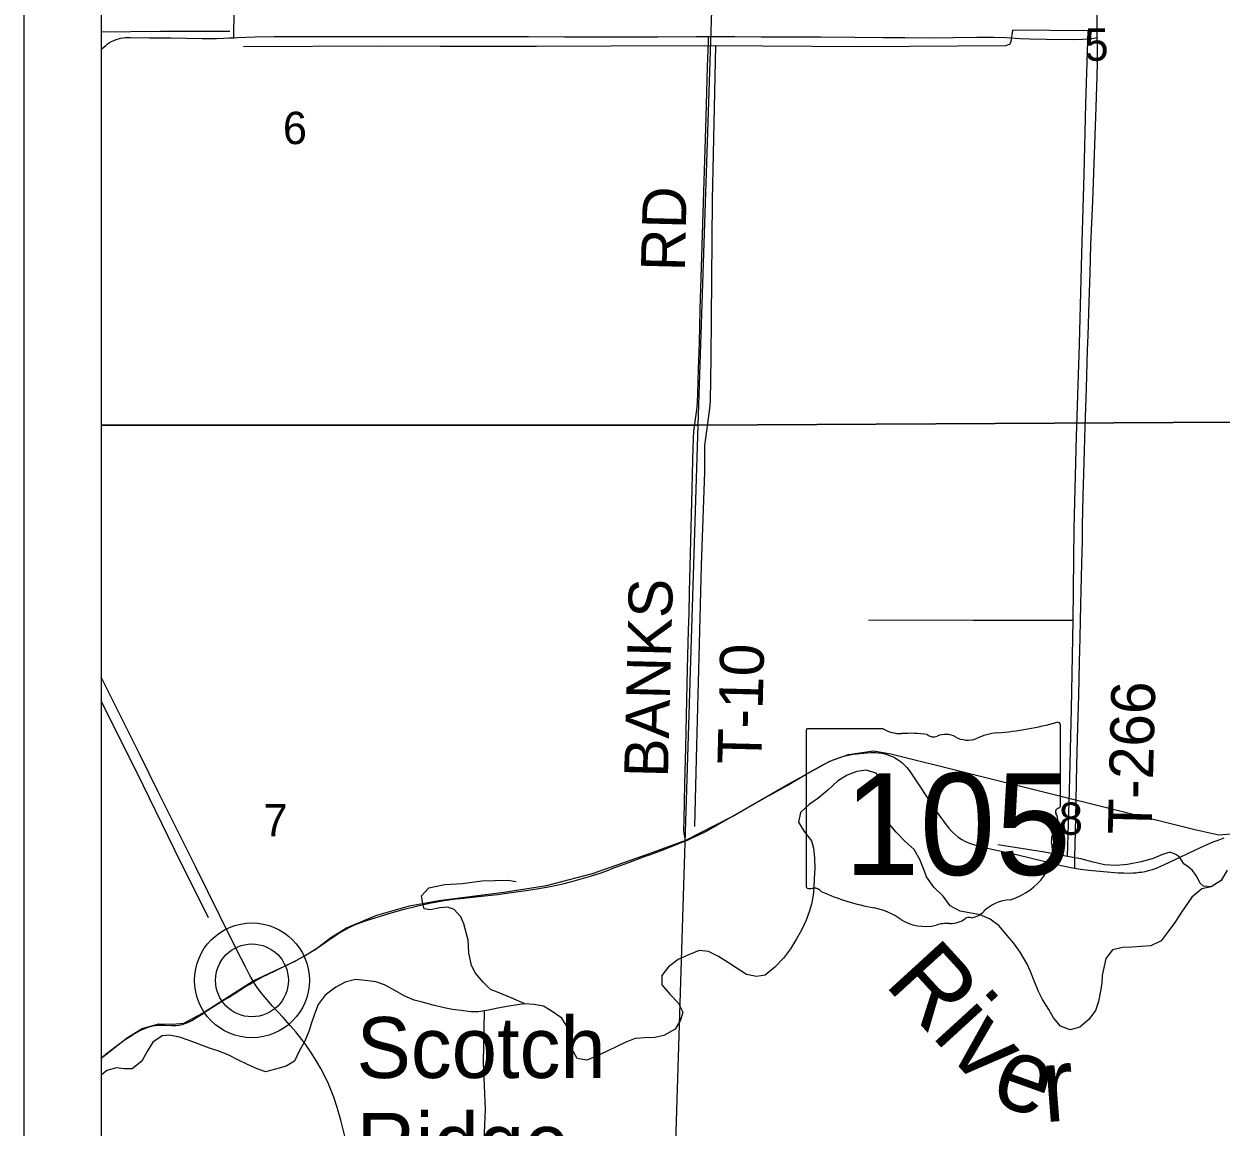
# Model space of a CAD drawing. Extents: x -8.3 to 42.1, y 0 to 22.
# Drawn here: x 2 to 3.551, y 16.412 to 17.841 of the extents above; entities that cross this region are included whole.
import ezdxf

# ---------------------------------------------------------------- set-up
doc = ezdxf.new("R2010")
doc.units = 0
for name, color, linetype in [('Default', 7, 'Continuous'), ('GM_X_Major_River', 7, 'Continuous'), ('GM_X_Major_River_Text', 7, 'Continuous'), ('GM_X_Minor_River', 7, 'Continuous'), ('GM_X_Rail_Line', 7, 'Continuous'), ('GM_X_Section', 7, 'Continuous'), ('GM_X_Section_Text', 7, 'Continuous'), ('GM_X_State_Location', 7, 'Continuous'), ('GM_X_State_Route', 7, 'Continuous'), ('GM_X_State_Shield', 7, 'Continuous'), ('GM_X_Township_Road', 7, 'Continuous'), ('GM_X_Township_Road_Text', 7, 'Continuous'), ('GM_X_Unincorporated', 7, 'Continuous'), ('GM_X_Unincorporated_Location', 7, 'Continuous'), ('GM_X_Unincorporated_Text', 7, 'Continuous'), ('SH_Cut_Line', 7, 'Continuous'), ('SH_Data', 7, 'Continuous')]:
    doc.layers.add(name, color=color, linetype=linetype)

msp = doc.modelspace()

# ---------------------------------------------------------------- linework, layer by layer
at = {"layer": 'Default'}
for points in [[(2.1, 18.3401), (2.1, 17.3208), (2.8735, 17.321), (2.9069, 18.3295)], [(2.1, 17.3208), (2.1, 16.3231), (2.8424, 16.322), (2.8735, 17.321)]]:
    msp.add_lwpolyline(points, close=True, dxfattribs=at)
at = {"layer": 'GM_X_Major_River'}
for points in [[(3.4997, 16.6901), (3.4911, 16.6766), (3.4825, 16.665), (3.4736, 16.653), (3.4602, 16.6464), (3.4476, 16.6455), (3.4358, 16.6446), (3.4237, 16.6441), (3.4103, 16.6413), (3.4018, 16.63), (3.3997, 16.6198), (3.3972, 16.6081), (3.3966, 16.5978), (3.3945, 16.5853), (3.3924, 16.574), (3.3884, 16.5627), (3.3798, 16.5507), (3.3682, 16.541), (3.3557, 16.5374), (3.3428, 16.5422), (3.3339, 16.5531), (3.3277, 16.5638), (3.3196, 16.5769), (3.3145, 16.5873), (3.309, 16.601), (3.3043, 16.6129), (3.2992, 16.6233), (3.2907, 16.6383), (3.2819, 16.6502), (3.2737, 16.6599), (3.2637, 16.6722), (3.2517, 16.6808), (3.2389, 16.6864), (3.2249, 16.6889), (3.2128, 16.6914), (3.2, 16.6981), (3.1908, 16.7109), (3.1788, 16.7225), (3.1696, 16.7356), (3.166, 16.7452), (3.1609, 16.7582), (3.1536, 16.7712), (3.1416, 16.7817), (3.1301, 16.7937), (3.1189, 16.8072), (3.1135, 16.8199), (3.113, 16.8321), (3.1143, 16.845), (3.1134, 16.8579), (3.1042, 16.8699), (3.0913, 16.8739), (3.0792, 16.8722), (3.0666, 16.8675), (3.0539, 16.8598), (3.0415, 16.8479), (3.0288, 16.8371), (3.0173, 16.8293), (3.0061, 16.8189), (3.0036, 16.8064), (3.0109, 16.7945), (3.0206, 16.7825), (3.023, 16.773), (3.0243, 16.7604), (3.0248, 16.7467), (3.0238, 16.7334), (3.0232, 16.722), (3.0227, 16.7122), (3.0206, 16.7004), (3.0173, 16.6906), (3.0133, 16.6797), (3.0074, 16.6665), (3.0011, 16.6556), (2.9933, 16.6424), (2.984, 16.6304), (2.9731, 16.6185), (2.9604, 16.6085), (2.949, 16.6068), (2.9361, 16.6093), (2.923, 16.6179), (2.9114, 16.625), (2.8997, 16.6324), (2.887, 16.6391), (2.8748, 16.6401), (2.8603, 16.6343), (2.8477, 16.6285), (2.835, 16.6192), (2.8264, 16.608), (2.8266, 16.5958), (2.8374, 16.5834), (2.8478, 16.5726), (2.8536, 16.5603), (2.8508, 16.5501), (2.8437, 16.5385), (2.8289, 16.5301), (2.8173, 16.5276), (2.804, 16.5271), (2.7919, 16.5262), (2.7789, 16.5211), (2.7689, 16.5163), (2.7548, 16.5094), (2.7417, 16.5032)], [(3.5589, 16.7446), (3.551, 16.7311), (3.5383, 16.7227), (3.5261, 16.72), (3.513, 16.7093), (3.4997, 16.6901)], [(2.7417, 16.5032), (2.7291, 16.4981), (2.7166, 16.5002), (2.7089, 16.5144), (2.7077, 16.5281), (2.7045, 16.54), (2.6967, 16.5527), (2.6833, 16.5621), (2.6731, 16.568), (2.6606, 16.5705), (2.6489, 16.5711), (2.6394, 16.5697), (2.6286, 16.5683), (2.6142, 16.5657), (2.6021, 16.5629), (2.5891, 16.5608), (2.5792, 16.561), (2.5664, 16.5624), (2.5554, 16.5637), (2.5444, 16.5659), (2.5301, 16.5695), (2.5176, 16.5728), (2.5055, 16.5761), (2.4935, 16.5813), (2.4807, 16.5884), (2.4672, 16.5958), (2.4559, 16.5998), (2.4422, 16.6016), (2.4294, 16.6026), (2.4164, 16.5991), (2.4041, 16.5929), (2.3903, 16.5825), (2.3813, 16.5705), (2.3765, 16.558), (2.3725, 16.5467), (2.3693, 16.5352), (2.3637, 16.5218), (2.3567, 16.5098), (2.3504, 16.497), (2.3396, 16.4903), (2.3259, 16.4864), (2.3129, 16.4832), (2.3023, 16.4869), (2.2888, 16.4932), (2.2779, 16.498), (2.2647, 16.5051), (2.2512, 16.5103), (2.2406, 16.5139), (2.2142, 16.5235), (2.2014, 16.5279), (2.1886, 16.5308), (2.179, 16.5299), (2.1669, 16.5214), (2.1601, 16.5101), (2.1526, 16.4969), (2.1403, 16.487), (2.1297, 16.4871), (2.1198, 16.4881), (2.1076, 16.4849), (2.1, 16.4789)]]:
    msp.add_lwpolyline(points, dxfattribs=at)
at = {"layer": 'GM_X_Minor_River'}
for points in [[(2.1, 17.8307), (2.1768, 17.8316), (2.2667, 17.8317)], [(3.3519, 16.7622), (3.3547, 16.8469), (3.3573, 16.9533), (3.3595, 17.0681), (3.3606, 17.1874), (3.3636, 17.3064), (3.3678, 17.426), (3.3707, 17.5434), (3.3736, 17.646), (3.3759, 17.7372), (3.3789, 17.8318), (3.281, 17.8327), (3.2787, 17.8183), (3.2775, 17.8145), (3.2721, 17.8124), (3.0849, 17.8113), (2.9574, 17.8119), (2.8959, 17.8125), (2.76, 17.8119), (2.664, 17.8116), (2.5398, 17.8117), (2.4639, 17.812), (2.2844, 17.8111)], [(2.8959, 17.8125), (2.8918, 17.6127), (2.8901, 17.4082), (2.8893, 17.3523), (2.8882, 17.3424), (2.8858, 17.3231), (2.8816, 17.2947), (2.8817, 17.2605), (2.8775, 17.1393), (2.8745, 17.0208), (2.8716, 16.906), (2.8686, 16.8008)], [(3.3595, 17.0681), (3.23, 17.068), (3.0941, 17.0685)], [(2.2393, 16.6827), (2.1952, 16.7711), (2.1464, 16.8713), (2.1015, 16.9608), (2.1, 16.9637)], [(3.5029, 16.7524), (3.4976, 16.7607), (3.4932, 16.7643), (3.4853, 16.7675), (3.4753, 16.7648), (3.463, 16.7594), (3.4474, 16.7553), (3.4298, 16.7516), (3.4153, 16.7505), (3.4002, 16.7513), (3.3855, 16.7548), (3.3693, 16.7591), (3.3519, 16.7622), (3.3221, 16.7676), (3.2616, 16.7774)], [(3.5383, 16.7227), (3.5281, 16.7237), (3.5237, 16.728), (3.5197, 16.7361), (3.5142, 16.7438), (3.5086, 16.7485), (3.5029, 16.7524)], [(2.6489, 16.5711), (2.6312, 16.5791), (2.6135, 16.5864), (2.6045, 16.5897), (2.5949, 16.5991), (2.585, 16.6108), (2.58, 16.6209), (2.5766, 16.6373), (2.5756, 16.6537), (2.5701, 16.6748), (2.5662, 16.684), (2.5574, 16.6934), (2.5491, 16.6963), (2.5388, 16.6954), (2.5262, 16.6928), (2.5187, 16.6941), (2.517, 16.701), (2.5153, 16.7113), (2.5244, 16.7213), (2.5454, 16.726), (2.5678, 16.7273), (2.5933, 16.7304), (2.61, 16.731), (2.6271, 16.7313), (2.6377, 16.7299)], [(2.5965, 16.562), (2.595, 16.4953), (2.5974, 16.4348), (2.5947, 16.3634), (2.5957, 16.306), (2.5942, 16.2418), (2.5941, 16.1558)]]:
    msp.add_lwpolyline(points, dxfattribs=at)
at = {"layer": 'GM_X_Rail_Line'}
msp.add_lwpolyline([(2.1, 16.5008), (2.134, 16.5277), (2.1533, 16.5393), (2.1749, 16.5454), (2.1926, 16.5447), (2.2073, 16.5462), (2.2312, 16.5593), (2.2968, 16.601), (2.3515, 16.6265), (2.377, 16.6411), (2.3978, 16.6573), (2.4179, 16.6697), (2.4572, 16.6859), (2.4997, 16.6982), (2.5375, 16.7052), (2.6216, 16.716), (2.6771, 16.7245), (2.7365, 16.7399), (2.809, 16.7654), (2.8576, 16.7831), (2.9178, 16.814), (2.9872, 16.8541), (3.0443, 16.8858), (3.0682, 16.8943), (3.1007, 16.8989), (3.123, 16.895), (3.5172, 16.797), (3.5481, 16.7901), (3.5751, 16.7924)], dxfattribs=at)
at = {"layer": 'GM_X_Section'}
for points in [[(2.9069, 18.3295), (2.9164, 18.3298), (3.9047, 18.3241), (3.8739, 17.3266), (2.8735, 17.321)], [(3.8739, 17.3266), (3.8435, 16.3264), (2.8424, 16.322), (2.8735, 17.321)]]:
    msp.add_lwpolyline(points, close=True, dxfattribs=at)
at = {"layer": 'GM_X_State_Route'}
for points in [[(2.2975, 16.5996), (2.2964, 16.6013), (2.2926, 16.608), (2.2869, 16.619), (2.2814, 16.6301), (2.2695, 16.6537), (2.2225, 16.7483), (2.1919, 16.8095), (2.1741, 16.8458), (2.1507, 16.8932), (2.1241, 16.9459), (2.1, 16.9945)], [(3.0262, 16.8759), (3.0341, 16.8803), (3.0387, 16.8827), (3.043, 16.8848), (3.0483, 16.8872), (3.0525, 16.8887), (3.057, 16.8903), (3.0625, 16.892), (3.068, 16.8934), (3.0743, 16.8946), (3.0792, 16.8952), (3.0834, 16.8957), (3.0876, 16.8962), (3.0921, 16.8966), (3.0972, 16.8968), (3.1007, 16.8968), (3.1038, 16.8967), (3.107, 16.8964), (3.1114, 16.8959), (3.1153, 16.895), (3.1191, 16.8939), (3.1225, 16.8927), (3.1253, 16.8915), (3.1282, 16.8899), (3.1326, 16.8873), (3.1351, 16.8855), (3.1375, 16.8837), (3.14, 16.8814), (3.142, 16.8793), (3.1438, 16.8773), (3.1474, 16.8729), (3.1517, 16.8667)], [(2.5278, 16.7019), (2.5329, 16.7029), (2.5439, 16.7049), (2.5537, 16.7065), (2.5599, 16.7073), (2.5655, 16.7078), (2.5927, 16.7106), (2.6137, 16.713), (2.6254, 16.7146), (2.6537, 16.7184), (2.6697, 16.721), (2.6819, 16.7233), (2.6982, 16.7268), (2.7097, 16.7295), (2.7341, 16.7367), (2.7477, 16.7411), (2.7559, 16.744), (2.7645, 16.7474), (2.7838, 16.7545), (2.8042, 16.762), (2.8106, 16.7644), (2.8211, 16.7683), (2.8367, 16.7744), (2.8454, 16.7778), (2.8573, 16.7824), (2.8588, 16.7829), (2.865, 16.7857), (2.8746, 16.79), (2.8845, 16.7951), (2.9191, 16.8147), (2.9341, 16.8236), (2.9476, 16.8311), (2.9742, 16.8461), (2.9888, 16.8543), (3.0136, 16.8686), (3.0227, 16.874), (3.0262, 16.8759)], [(3.1517, 16.8667), (3.163, 16.8496), (3.1779, 16.8266), (3.1853, 16.8159), (3.1935, 16.805), (3.1985, 16.7987), (3.2026, 16.7942), (3.2067, 16.7904), (3.2104, 16.7873), (3.2151, 16.7843), (3.2199, 16.7817), (3.225, 16.7795), (3.2302, 16.7777), (3.2375, 16.7755), (3.2447, 16.7738), (3.2641, 16.7695), (3.2858, 16.7646), (3.3444, 16.7505), (3.3566, 16.7479), (3.3616, 16.7471), (3.3688, 16.7459), (3.3799, 16.7444), (3.3986, 16.7426), (3.4179, 16.7411), (3.425, 16.7408), (3.4325, 16.7406), (3.4368, 16.7408), (3.441, 16.7411), (3.4447, 16.7416), (3.4479, 16.742), (3.4527, 16.7428), (3.4572, 16.7439), (3.462, 16.7453), (3.4672, 16.7471), (3.4728, 16.7495), (3.4833, 16.7542), (3.499, 16.7617), (3.5169, 16.7703), (3.53, 16.7762), (3.5408, 16.781), (3.546, 16.783), (3.5507, 16.7847), (3.5552, 16.7863)], [(2.2975, 16.5996), (2.306, 16.6045), (2.3092, 16.6062), (2.3255, 16.614), (2.335, 16.6186), (2.3527, 16.6275), (2.362, 16.6325), (2.3701, 16.6372), (2.3805, 16.6438), (2.3948, 16.6537), (2.4067, 16.6617), (2.4136, 16.6659), (2.4203, 16.6695), (2.4276, 16.673), (2.4363, 16.6765), (2.444, 16.6793), (2.4564, 16.6831), (2.4743, 16.6885), (2.482, 16.6909), (2.4928, 16.6939), (2.5067, 16.6974), (2.5176, 16.6998), (2.5278, 16.7019)], [(2.1, 16.501), (2.1067, 16.5064), (2.1195, 16.5163), (2.131, 16.5248), (2.1414, 16.5316), (2.1474, 16.5351), (2.1525, 16.5376), (2.1574, 16.5398), (2.1621, 16.5414), (2.1664, 16.5426), (2.1699, 16.5432), (2.1743, 16.5436), (2.1787, 16.5435), (2.1824, 16.5435), (2.1911, 16.5432), (2.1973, 16.5432), (2.2009, 16.5436), (2.205, 16.5445), (2.2097, 16.546), (2.2124, 16.5472), (2.2174, 16.5497), (2.2237, 16.5536), (2.2321, 16.5588), (2.2362, 16.5615), (2.2377, 16.5624), (2.2445, 16.5667), (2.256, 16.5741), (2.265, 16.5796), (2.2797, 16.5887), (2.2859, 16.5928), (2.2927, 16.5968), (2.2975, 16.5996)], [(2.4164, 16.3979), (2.4105, 16.4205), (2.4057, 16.4369), (2.4014, 16.4503), (2.3981, 16.4591), (2.3945, 16.4677), (2.3898, 16.4775), (2.3847, 16.4872), (2.3784, 16.498), (2.3726, 16.5072), (2.3664, 16.5162), (2.3599, 16.525), (2.3521, 16.5347), (2.3451, 16.543), (2.3357, 16.5534), (2.3221, 16.5683), (2.3119, 16.58), (2.3061, 16.5873), (2.3015, 16.5935), (2.2975, 16.5996)]]:
    msp.add_lwpolyline(points, dxfattribs=at)
at = {"layer": 'GM_X_State_Shield'}
for p, q in [((3.0133, 16.9242), (3.0133, 16.7241)), ((3.1131, 16.9277), (3.0166, 16.9277)), ((3.3429, 16.828), (3.3429, 16.9326)), ((3.3429, 16.828), (3.3429, 16.828))]:
    msp.add_line(p, q, dxfattribs=at)
for centre, major_axis, start_param, end_param in [((3.0171, 16.9247), (0.00382, 0), 1.712693, 3.28349), ((3.1361, 16.9509), (0.037, 0), 4.042523, 4.731795), ((3.1484, 16.8153), (0.133, 0), 1.404758, 1.657858), ((3.2701, 16.8666), (0.0703, 0), 1.699011, 2.107814), ((3.2255, 17.2005), (0.3495, 0), 4.814394, 5.042369), ((3.3392, 16.9331), (0.00367, 0), 6.141152, 7.989035), ((3.1785, 16.9257), (0.0107, 0), 3.836095, 5.185415), ((3.1942, 16.9026), (0.0222, 0), 0.950623, 2.079405), ((3.2229, 16.9343), (0.0267, 0), 4.081561, 5.145723), ((3.3421, 16.8203), (0.00568, 0), 1.883978, 3.671073), ((3.3059, 16.807), (0.0341, 0), 5.934695, 6.695948), ((3.339, 16.8276), (0.00393, 0), 5.05454, 6.418171), ((3.3561, 16.7842), (0.0248, 0), 2.387724, 3.262537), ((3.2451, 16.7708), (0.0874, 0), 5.101752, 6.440018), ((3.0171, 16.7237), (0.00385, 0), 3.00124, 4.508301), ((3.0177, 16.7442), (0.0294, 0), 4.665946, 4.897461), ((3.0237, 16.7126), (0.0106, 0), 0.519207, 1.627899), ((3.1576, 16.8924), (0.2524, 0), 4.195997, 4.488961), ((3.2819, 16.6679), (0.0479, 0), 1.647645, 2.488434), ((3.0823, 16.6342), (0.079, 0), 0.823519, 1.323587), ((3.2213, 16.7047), (0.0282, 0), 4.937069, 5.64225), ((3.1677, 16.7116), (0.0501, 0), 4.026481, 4.996735), ((3.1967, 16.6424), (0.0412, 0), 1.495662, 1.94098), ((3.2003, 16.6966), (0.0267, 0), 4.691044, 5.507374), ((3.2245, 16.6772), (0.00752, 0), 1.147584, 2.315152)]:
    msp.add_ellipse(centre, major_axis=major_axis, ratio=0.8, start_param=start_param, end_param=end_param, dxfattribs=at)
at = {"layer": 'GM_X_Township_Road'}
for points in [[(3.9382, 20.9), (2.1, 20.9), (2.1, 15.312)], [(2.2719, 17.823), (2.2721, 17.8314), (2.2725, 17.8501), (2.2734, 17.8843), (2.274, 17.9155), (2.2748, 17.9528), (2.2766, 18.0307), (2.2776, 18.0712), (2.2782, 18.0992), (2.2787, 18.1241), (2.2796, 18.1771), (2.2811, 18.2363), (2.2818, 18.2643), (2.2823, 18.2954), (2.2825, 18.311), (2.2828, 18.3172), (2.283, 18.3236), (2.2834, 18.33), (2.2836, 18.3338)], [(3.3907, 17.8234), (3.3905, 17.8317), (3.3905, 17.8535), (3.391, 17.8784), (3.3918, 17.9064), (3.3932, 17.9436), (3.3944, 17.9841), (3.3957, 18.0307), (3.3971, 18.0742), (3.3982, 18.1053), (3.3994, 18.1395), (3.4025, 18.2389), (3.4039, 18.2918), (3.4045, 18.3073), (3.405, 18.3166), (3.4054, 18.3223)], [(2.1, 17.8077), (2.1012, 17.809), (2.1059, 17.8131), (2.1084, 17.815), (2.1109, 17.8167), (2.1136, 17.8182), (2.1164, 17.8196), (2.1193, 17.8207), (2.1223, 17.8217), (2.1253, 17.8224), (2.1284, 17.8229), (2.1314, 17.8232), (2.1346, 17.8234), (2.1377, 17.8235), (2.1625, 17.823), (2.1905, 17.8227), (2.2309, 17.8222), (2.2495, 17.8221), (2.2589, 17.8223), (2.2661, 17.8227), (2.2719, 17.823)], [(2.2719, 17.823), (2.2773, 17.8234), (2.2992, 17.8241), (2.3241, 17.8244), (2.3925, 17.8246), (2.4547, 17.8245), (2.4889, 17.8245), (2.5541, 17.8246), (2.6101, 17.8246), (2.6536, 17.8245), (2.7002, 17.8243), (2.7375, 17.8242), (2.7655, 17.824), (2.8215, 17.8243), (2.8712, 17.8246), (2.8869, 17.8246)], [(2.8573, 16.7824), (2.8561, 16.7878), (2.8552, 16.7915), (2.855, 16.7968), (2.8554, 16.8095), (2.8563, 16.8562), (2.8575, 16.9028), (2.859, 16.965), (2.8597, 17.0053), (2.8612, 17.0552), (2.8618, 17.0769), (2.8625, 17.1049), (2.8635, 17.1546), (2.8656, 17.2386), (2.8665, 17.2757), (2.867, 17.2915), (2.8674, 17.3039), (2.8679, 17.3134), (2.8687, 17.319), (2.8703, 17.3286), (2.8718, 17.3409), (2.8726, 17.3502), (2.8733, 17.3626), (2.8742, 17.3937), (2.8751, 17.4279), (2.8762, 17.4714), (2.8775, 17.5119), (2.8808, 17.6238), (2.8829, 17.6922), (2.8838, 17.7202), (2.8858, 17.7855), (2.8867, 17.8072), (2.8869, 17.8196), (2.8869, 17.8246)], [(2.8869, 17.8246), (2.921, 17.8246), (2.9551, 17.8243), (2.9955, 17.8243), (3.0141, 17.8241), (3.0327, 17.8241), (3.0763, 17.8239), (3.1136, 17.8234), (3.1415, 17.8232), (3.1757, 17.823), (3.2037, 17.8233), (3.2348, 17.8238), (3.2565, 17.8236), (3.2721, 17.8231), (3.2907, 17.8219), (3.3031, 17.8215), (3.3249, 17.8213), (3.3591, 17.8209), (3.3715, 17.821), (3.3777, 17.8214), (3.3837, 17.822), (3.3883, 17.8229), (3.3907, 17.8234)], [(3.3616, 16.7471), (3.3617, 16.7528), (3.3617, 16.7608), (3.3628, 16.8122), (3.3643, 16.8806), (3.3655, 16.9303), (3.3666, 16.9708), (3.3676, 17.0143), (3.3683, 17.0454), (3.3694, 17.0889), (3.3708, 17.1416), (3.3714, 17.1709), (3.3716, 17.1915), (3.3723, 17.2288), (3.3741, 17.2879), (3.3748, 17.3189), (3.3765, 17.3687), (3.3781, 17.4184), (3.3787, 17.437), (3.3802, 17.4806), (3.3813, 17.5179), (3.3825, 17.5552), (3.3847, 17.6111), (3.3856, 17.6359), (3.3887, 17.7199), (3.3905, 17.7727), (3.3909, 17.7913), (3.391, 17.81), (3.3907, 17.8234)]]:
    msp.add_lwpolyline(points, dxfattribs=at)
at = {"layer": 'GM_X_Unincorporated'}
for radius in [0.0744, 0.0472]:
    msp.add_circle((2.2954, 16.6016), radius, dxfattribs=at)
at = {"layer": 'GM_X_Unincorporated_Location'}
msp.add_line((2.2954, 16.6016), (2.2954, 16.6016), dxfattribs=at)
at = {"layer": 'SH_Cut_Line'}
msp.add_lwpolyline([(7.9572, 20.9), (2.1, 20.9), (2.1, 14.1)], dxfattribs=at)
at = {"layer": 'SH_Data'}
for p, q in [((2, 21), (2, 14)), ((2.1, 20.9), (2.1, 14.1))]:
    msp.add_line(p, q, dxfattribs=at)

# ---------------------------------------------------------------- texts
at = {"layer": 'GM_X_Major_River_Text'}
for s, height, rotation, p in [('Riv', 0.09476, 312.4276, (3.1135, 16.5966)), ('e', 0.0948, 340.4288, (3.2495, 16.4453)), ('r', 0.0948, 4.4307, (3.3217, 16.4177))]:
    msp.add_text(s, height=height, rotation=rotation, dxfattribs=at).set_placement(p)
at = {"layer": 'GM_X_Section_Text'}
for s, p in [('5', (3.3742, 17.7932)), ('6', (2.3355, 17.6852)), ('7', (2.3105, 16.7882)), ('8', (3.3409, 16.7902))]:
    msp.add_text(s, height=0.0419, rotation=0, dxfattribs=at).set_placement(p)
at = {"layer": 'GM_X_State_Location'}
for s in ['s', 'r']:
    msp.add_text(s, height=0.000189, dxfattribs=at).set_placement((3.1744, 16.8109))
msp.add_text('105', height=0.000189, rotation=0, dxfattribs=at).set_placement((3.1076, 16.7971))
at = {"layer": 'GM_X_State_Shield'}
msp.add_text('105', height=0.13184, dxfattribs=at).set_placement((3.0625, 16.7382))
at = {"layer": 'GM_X_Township_Road_Text'}
for s, rotation, p in [('RD', 88.5193, (2.8561, 17.5199)), ('BANKS', 88.578, (2.8344, 16.8639)), ('T-10', 88.585, (2.9553, 16.881)), ('T-266', 88.6099, (3.4611, 16.7899))]:
    msp.add_text(s, height=0.05682, rotation=rotation, dxfattribs=at).set_placement(p)
at = {"layer": 'GM_X_Unincorporated_Text'}
for s, p in [('Scotch', (2.4309, 16.4751)), ('Ridge', (2.4309, 16.3509))]:
    msp.add_text(s, height=0.07898, rotation=0, dxfattribs=at).set_placement(p)

doc.saveas('drawing.dxf')
